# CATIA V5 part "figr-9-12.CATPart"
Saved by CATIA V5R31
Part number: Part2
Bounding box of the stored display mesh (mm): x -96.75 to 0, y -83.031 to 83.031, z -58.031 to 58.031
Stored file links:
  D:\PROJECTS\Project 2021\US EDITION\CATIA V5 6R 2021\Resources\Part Files\c09_catia_v5_6r2021_prt\c09_catia_v5_6r2021_prt\figr-9-12.CATPart
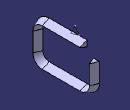
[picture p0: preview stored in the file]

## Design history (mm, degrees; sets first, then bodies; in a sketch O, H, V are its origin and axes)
Body1 (main body)
  Sketch1 on yz-plane, origin (0, 0, 0), H (0, 1, 0), V (0, 0, 1)
    point P1 (-75, 50)
    line L1 (-50, 50) -> (50, 50)
    line L2 (75, 25) -> (75, -25)
    line L3 (50, -50) -> (-50, -50)
    line L4 (-75, -25) -> (-75, 25)
    point P2 (75, 50)
    point P3 (75, -50)
    arc A1 centre (-50, 25) radius 25 from (-50, 50) to (-75, 25) ccw
    arc A2 centre (-50, -25) radius 25 from (-50, -50) to (-75, -25) cw
    arc A3 centre (50, -25) radius 25 from (50, -50) to (75, -25) ccw
    distance V L4 = 75
    distance H L1 = 50
    distance P1 P2 = 150
    radius A1 = 25
    radius A2 = 25
    distance P2 P3 = 100
    radius A3 = 25
    horizontal: L1 H, L3 H
    vertical: L2 V, L4 V
    coincidence: L1 P1, L4 P1, L3 P3, L2 P3, L2 P2, L1 P2
    tangency: A1 L1, A1 L4, A2 L3, A2 L4, A3 L3, A3 L2
  Plane1: type Angle, RefPlane yz-plane, Direction Sketch1.V, Angle 31
  Plane2: type Offset, RefPlane Plane1, Offset -108
  Sketch2 on Plane2, origin (-92.5741, -55.6241, 0), H (-0.515, 0.8572, 0), V (0, 0, 1)
    line L1 (0, 0) -> (-8.0309, -18.5626)
    line L2 (-8.0309, -18.5626) -> (8.1085, -18.5626)
    line L3 (8.1085, -18.5626) -> (0, 0)
    horizontal: L2 H
  Rib1: profile Sketch2, centre curve Sketch1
